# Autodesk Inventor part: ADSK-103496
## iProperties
Shininess: 0.0
Created: 2000-10
Part Number: ADSK-103496
Checked By: PT
Description: SPAENAUR INC.
Document SubType Name: Modeling
Designer: Gary
Stock Number: ADSK-103496
Density: 1 g/cm^3
Density: 0.0
Volumn: 0.0
Area: 0.0
PropertySet Name: Model Information
Control State: 0
Master: False
Checked Out: False
Title: CARBIN LOCK
Author: Gary
